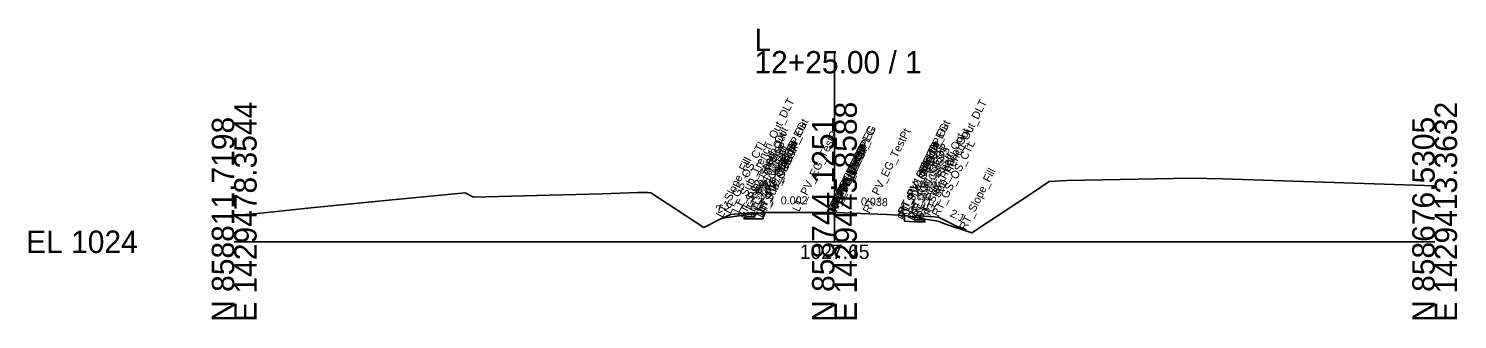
# Model space of a CAD drawing. Extents: x -26 to 176, y -10 to 13058.
# Drawn here: x -25.7 to 152.8, y 1490.3 to 1526.6 of the extents above; entities that cross this region are included whole.
import ezdxf

# ---------------------------------------------------------------- set-up
doc = ezdxf.new("R2010")
doc.units = 0
for name, color, linetype in [('Default', 7, 'Continuous'), ('Exist Cross Section Cell', 7, 'Continuous'), ('Exist XS Center Line Elevation Label', 7, 'Continuous'), ('Exist XS Ground Line', 7, 'Continuous'), ('Old_Level_50', 7, 'Continuous'), ('Prop CMT Pvmt Course 1', 7, 'Continuous'), ('Prop CMT Pvmt Course 2', 7, 'Continuous'), ('Prop CMT Shld Paved Course 1', 7, 'Continuous'), ('Prop CMT Shld Paved Course 2', 7, 'Continuous'), ('Prop CMT Slope Grass', 7, 'Continuous'), ('Prop CMT Subgrade Earthwork', 7, 'Continuous'), ('Prop XS Dump Level', 7, 'Continuous'), ('Prop XS SE Text', 7, 'Continuous'), ('Prop XS Side Slope Text', 7, 'Continuous')]:
    doc.layers.add(name, color=color, linetype=linetype)

msp = doc.modelspace()

# ---------------------------------------------------------------- linework, layer by layer
at = {"layer": 'Exist Cross Section Cell'}
for p, q in [((75, 1500), (75, 1523.82)), ((0, 1500), (75, 1500)), ((75, 1500), (150, 1500))]:
    msp.add_line(p, q, dxfattribs=at)
at = {"layer": 'Exist XS Ground Line'}
msp.add_lwpolyline([(0, 1503.29), (3.32, 1503.57), (9.98, 1504.29), (19.3, 1505.18), (28.85, 1506.1), (29.89, 1505.58), (36.2, 1505.74), (45.97, 1505.99), (50.43, 1506.16), (51.72, 1506.15), (52.07, 1506.13), (58.69, 1501.79), (60.95, 1502.93), (63.06, 1503.23), (66.11, 1503.67), (72.62, 1503.66), (75.1, 1503.65), (81.49, 1503.39), (83.76, 1503.3), (85.55, 1502.96), (87.94, 1502.56), (88.86, 1502.21), (92.16, 1501.1), (99.87, 1506.19), (101.83, 1507.51), (104.08, 1507.64), (119.53, 1507.94), (123.54, 1507.86), (144.94, 1507.17), (150, 1506.99)], dxfattribs=at)
at = {"layer": 'Old_Level_50'}
for points in [[(63.06, 1503.23), (65, 1503.51), (65, 1503.66), (62, 1503.42), (61.03, 1502.94)], [(63.06, 1503.23), (65, 1503.51), (65, 1503.66), (62, 1503.42), (61.03, 1502.94)], [(63.06, 1503.23), (65, 1503.51), (65, 1503.66), (62, 1503.42), (61.03, 1502.94)], [(65, 1503.51), (66.11, 1503.67), (66.13, 1503.67), (66.11, 1502.87), (65, 1502.87), (63.69, 1502.85), (63.95, 1503.1), (64.45, 1503.11), (65, 1503.12)], [(65, 1503.51), (66.11, 1503.67), (66.13, 1503.67), (66.11, 1502.87), (65, 1502.87), (63.69, 1502.85), (63.95, 1503.1), (64.45, 1503.11), (65, 1503.12)], [(65, 1503.51), (66.11, 1503.67), (66.13, 1503.67), (66.11, 1502.87), (65, 1502.87), (63.69, 1502.85), (63.95, 1503.1), (64.45, 1503.11), (65, 1503.12)], [(83.75, 1503.3), (83.76, 1503.3), (85, 1503.06), (85, 1502.76), (85.55, 1502.75), (86.05, 1502.74), (86.31, 1502.48), (85, 1502.51), (83.76, 1502.56)], [(83.75, 1503.3), (83.76, 1503.3), (85, 1503.06), (85, 1502.76), (85.55, 1502.75), (86.05, 1502.74), (86.31, 1502.48), (85, 1502.51), (83.76, 1502.56)], [(83.75, 1503.3), (83.76, 1503.3), (85, 1503.06), (85, 1502.76), (85.55, 1502.75), (86.05, 1502.74), (86.31, 1502.48), (85, 1502.51), (83.76, 1502.56)], [(88.86, 1502.21), (91.42, 1501.35), (88, 1503.06), (85, 1503.3), (85, 1503.06), (85.55, 1502.96), (87.94, 1502.56)], [(88.86, 1502.21), (91.42, 1501.35), (88, 1503.06), (85, 1503.3), (85, 1503.06), (85.55, 1502.96), (87.94, 1502.56)], [(88.86, 1502.21), (91.42, 1501.35), (88, 1503.06), (85, 1503.3), (85, 1503.06), (85.55, 1502.96), (87.94, 1502.56)]]:
    msp.add_lwpolyline(points, close=True, dxfattribs=at)
at = {"layer": 'Prop CMT Pvmt Course 1'}
msp.add_lwpolyline([(65, 1503.66), (65, 1503.12)], dxfattribs=at)
at = {"layer": 'Prop CMT Pvmt Course 2'}
for points in [[(65, 1502.87), (66.11, 1502.87)], [(85, 1502.51), (83.76, 1502.56)]]:
    msp.add_lwpolyline(points, dxfattribs=at)
at = {"layer": 'Prop CMT Shld Paved Course 1'}
for points in [[(65, 1503.66), (65, 1503.66)], [(85, 1503.3), (85, 1503.3)], [(85, 1502.76), (85, 1503.3)]]:
    msp.add_lwpolyline(points, dxfattribs=at)
at = {"layer": 'Prop CMT Shld Paved Course 2'}
for points in [[(65, 1503.12), (64.45, 1503.11), (63.95, 1503.1), (63.69, 1502.85)], [(63.69, 1502.85), (65, 1502.87)], [(85, 1502.76), (85.55, 1502.75), (86.05, 1502.74), (86.31, 1502.48)], [(86.31, 1502.48), (85, 1502.51)]]:
    msp.add_lwpolyline(points, dxfattribs=at)
at = {"layer": 'Prop CMT Slope Grass'}
for points in [[(65, 1503.66), (62, 1503.42), (61.03, 1502.94)], [(85, 1503.3), (88, 1503.06), (91.42, 1501.35)]]:
    msp.add_lwpolyline(points, dxfattribs=at)
at = {"layer": 'Prop CMT Subgrade Earthwork'}
for points in [[(66.11, 1502.87), (66.13, 1503.67)], [(83.76, 1502.56), (83.75, 1503.3)]]:
    msp.add_lwpolyline(points, dxfattribs=at)

# ---------------------------------------------------------------- texts
at = {"layer": 'Default'}
msp.add_text('-', height=0.0001, dxfattribs=at).set_placement((0, 1500))
at = {"layer": 'Exist Cross Section Cell'}
for s, p in [('L', (65, 1523.82)), ('12+25.00 / 1', (65, 1521.02)), ('EL 1024', (-26, 1498.6))]:
    msp.add_text(s, height=2.8, dxfattribs=at).set_placement(p)
for s, p in [('E 1429478.3544', (2.8, 1490)), ('E 1429445.8588', (77.8, 1490)), ('E 1429413.3632', (152.8, 1490)), ('N 858811.7198', (0, 1490)), ('N 858744.1251', (75, 1490)), ('N 858676.5305', (150, 1490))]:
    msp.add_text(s, height=2.8, rotation=90, dxfattribs=at).set_placement(p)
at = {"layer": 'Exist XS Center Line Elevation Label'}
msp.add_text('1027.65', height=1.8, dxfattribs=at).set_placement((70.67, 1497.85))
msp.add_text('1027.65', height=1.8, dxfattribs=at).set_placement((70.67, 1497.85))
msp.add_text('1027.65', height=1.8, dxfattribs=at).set_placement((70.67, 1497.85))
at = {"layer": 'Prop XS Dump Level'}
for s, p in [('LT_Sub_Trench_Out_DLT', (63.03, 1503.51)), ('RT_Sub_Trench_Out_DLT', (86.97, 1503.14)), ('LT_Sub_Trench_Out', (63.69, 1502.85)), ('LT_PV_OEEOP_EG', (66.11, 1503.67)), ('LT_PV_Sub_Tie_Out', (66.13, 1503.67)), ('LT_PV_EG_TestPt', (70.56, 1503.66)), ('RT_PV_IEEOP_EG', (75, 1503.65)), ('LT_PV_IEEOP_EG', (75, 1503.65)), ('RT_PV_EG_TestPt', (79.38, 1503.47)), ('RT_PV_Sub_Tie_Out', (83.75, 1503.3)), ('RT_PV_OEEOP_EG', (83.76, 1503.3)), ('RT_Sub_Trench_Out', (86.31, 1502.48)), ('LT_GS_OS_CTL', (62, 1503.42)), ('LT_PS2_Shelf_Out', (63.95, 1503.1)), ('LT_PV1_OEOT', (65, 1503.66)), ('LT_PS1_OEOP', (65, 1503.66)), ('LT_PV1_OEEOP', (66.11, 1503.54)), ('LT_PV2_OEEOP', (66.11, 1503.12)), ('LT_Sub_OEEOP', (66.11, 1502.87)), ('RT_PV1_IEEOP', (75, 1503.56)), ('LT_PV1_IEEOP', (75, 1503.56)), ('RT_PV2_IEEOP', (75, 1503.14)), ('RT_PV1_OEEOP', (83.76, 1503.22)), ('RT_PV2_OEEOP', (83.76, 1502.81)), ('RT_Sub_OEEOP', (83.76, 1502.56)), ('RT_PV1_OEOT', (85, 1503.3)), ('RT_PS1_OEOP', (85, 1503.3)), ('RT_PS2_Shelf_Out', (86.05, 1502.74)), ('RT_GS_OS_CTL', (88, 1503.06)), ('LT_Slope_Fill', (61.03, 1502.94)), ('LT_PS2_OEOP', (64.45, 1503.11)), ('LT_PV2_OEOT', (65, 1503.12)), ('LT_Sub_OEOT', (65, 1502.87)), ('LT_PV2_IEEOP', (75, 1503.14)), ('RT_PV2_OEOT', (85, 1502.76)), ('RT_Sub_OEOT', (85, 1502.51)), ('RT_PS2_OEOP', (85.55, 1502.75)), ('PV1_PGL', (75, 1503.68)), ('RT_Slope_Fill', (91.42, 1501.35)), ('PV2_PGL', (75, 1503.14))]:
    msp.add_text(s, height=1, rotation=63.5833, dxfattribs=at).set_placement(p)
at = {"layer": 'Prop XS SE Text'}
for s, rotation, p in [('0.002', 0.0917, (68.29, 1504.67)), ('0.038', 357.8238, (78.3, 1504.56))]:
    msp.add_text(s, height=1, rotation=rotation, dxfattribs=at).set_placement(p)
at = {"layer": 'Prop XS Side Slope Text'}
for rotation, p in [(26.565, (60.47, 1503.5)), (333.4349, (89.34, 1503.23))]:
    msp.add_text('2:1', height=1, rotation=rotation, dxfattribs=at).set_placement(p)

doc.saveas('drawing.dxf')
